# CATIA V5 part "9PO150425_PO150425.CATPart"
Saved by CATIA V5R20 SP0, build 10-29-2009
Part number: 9PO150425_PO150425
Revision: ANY
Definition: UNKNOWN
Nomenclature: 9PO150425_PO150425
Source: Unknown
Bounding box of the stored display mesh (mm): x -3.804 to 3.804, y 0 to 14.5, z -4 to 4
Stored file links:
  C:\Users\Utente\Desktop\IO LAVORO\3D X SITO CF\CUMSA\3D files PO\PO 150425\9PO150425_PO150425.CATPart
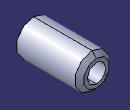
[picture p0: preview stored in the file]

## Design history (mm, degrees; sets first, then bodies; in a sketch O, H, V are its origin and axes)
Body1 "Chaflán2" (main body)
  Solid1: solid without history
